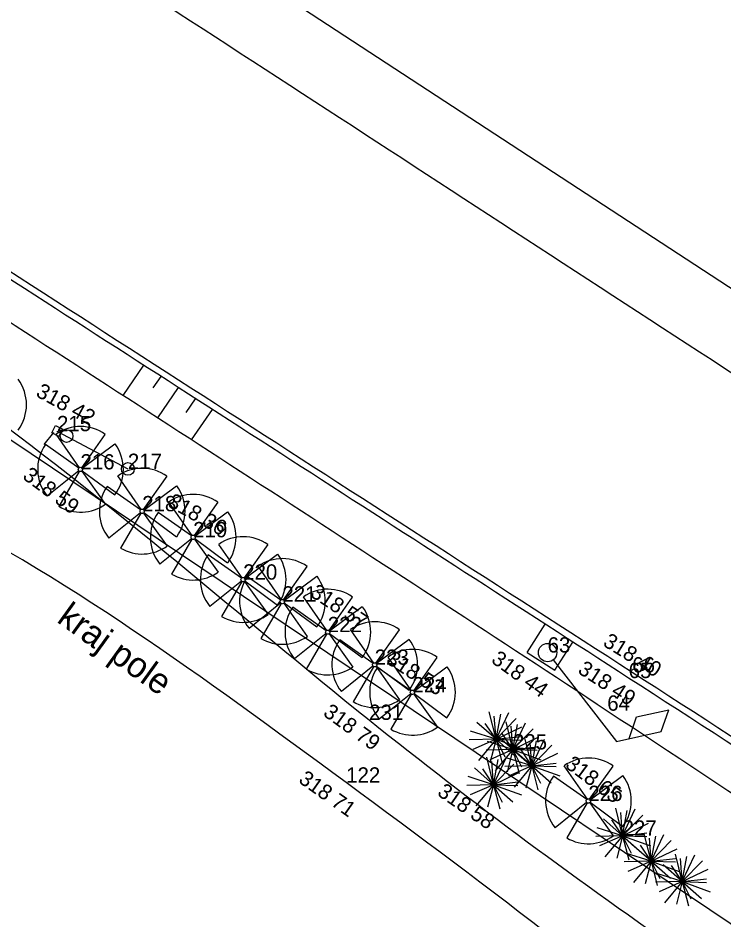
# Model space of a CAD drawing. Extents: x -742884 to -742543, y -1054677 to -1054433.
# Drawn here: x -742695.71 to -742681.87, y -1054513.42 to -1054495.74 of the extents above; entities that cross this region are included whole.
import ezdxf

# ---------------------------------------------------------------- set-up
doc = ezdxf.new("R2010")
doc.units = 0
for name, color, linetype in [('Vrstva 1', 7, 'Continuous'), ('Vrstva 10', 7, 'Continuous'), ('Vrstva 11', 7, 'Continuous'), ('Vrstva 12', 7, 'Continuous'), ('Vrstva 15', 7, 'Continuous'), ('Vrstva 16', 7, 'Continuous'), ('Vrstva 2', 7, 'Continuous'), ('Vrstva 3', 7, 'Continuous'), ('Vrstva 4', 7, 'Continuous'), ('Vrstva 50', 7, 'Continuous'), ('Vrstva 8', 7, 'Continuous')]:
    doc.layers.add(name, color=color, linetype=linetype)

# ---------------------------------------------------------------- blocks, each defined once
blk = doc.blocks.new('Z15')
at = {"layer": 'Vrstva 2'}
for p, q in [((-10, 2), (-8, 6)), ((-10, -2), (-10, 2)), ((-8, 6), (-6, 8)), ((-6, 8), (-2, 10)), ((-2, 10), (2, 10)), ((2, 10), (6, 8)), ((6, 8), (8, 6)), ((8, 6), (10, 2)), ((10, 2), (10, -2)), ((-8, -6), (-10, -2)), ((-6, -8), (-8, -6)), ((-2, -10), (-6, -8)), ((2, -10), (-2, -10)), ((6, -8), (2, -10)), ((8, -6), (6, -8)), ((10, -2), (8, -6))]:
    blk.add_line(p, q, dxfattribs=at)

msp = doc.modelspace()

# ---------------------------------------------------------------- linework, layer by layer
at = {"layer": 'Vrstva 1'}
for p, q in [((-742694.95, -1054503.84), (-742694.95, -1054503.84)), ((-742693.56, -1054504.58), (-742693.56, -1054504.58)), ((-742694.49, -1054504.59), (-742694.49, -1054504.59)), ((-742693.28, -1054505.41), (-742693.28, -1054505.41)), ((-742692.28, -1054505.92), (-742692.28, -1054505.92)), ((-742691.3, -1054506.75), (-742691.3, -1054506.75)), ((-742690.53, -1054507.18), (-742690.53, -1054507.18)), ((-742689.64, -1054507.78), (-742689.64, -1054507.78)), ((-742685.33, -1054508.18), (-742685.33, -1054508.18)), ((-742688.72, -1054508.42), (-742688.72, -1054508.42)), ((-742683.67, -1054508.57), (-742683.67, -1054508.57)), ((-742683.74, -1054508.68), (-742683.74, -1054508.68)), ((-742687.98, -1054508.96), (-742687.98, -1054508.96)), ((-742684.16, -1054509.32), (-742684.16, -1054509.32)), ((-742688.83, -1054509.5), (-742688.83, -1054509.5)), ((-742686.01, -1054510.08), (-742686.01, -1054510.08)), ((-742689.28, -1054510.73), (-742689.28, -1054510.73)), ((-742684.53, -1054511.09), (-742684.53, -1054511.09)), ((-742683.86, -1054511.77), (-742683.86, -1054511.77))]:
    msp.add_line(p, q, dxfattribs=at)
at = {"layer": 'Vrstva 10'}
for p, q in [((-742694.51, -1054504.557), (-742694.967, -1054503.898)), ((-742694.465, -1054504.557), (-742694.002, -1054503.904)), ((-742694.523, -1054504.562), (-742695.175, -1054504.103)), ((-742694.458, -1054504.566), (-742693.814, -1054504.089)), ((-742694.524, -1054504.619), (-742695.143, -1054505.116)), ((-742694.515, -1054504.627), (-742694.912, -1054505.315)), ((-742694.462, -1054504.624), (-742694.001, -1054505.274)), ((-742694.454, -1054504.615), (-742693.814, -1054505.088)), ((-742693.3, -1054505.377), (-742693.757, -1054504.718)), ((-742693.255, -1054505.377), (-742692.792, -1054504.724)), ((-742693.313, -1054505.382), (-742693.965, -1054504.923)), ((-742693.248, -1054505.386), (-742692.604, -1054504.909)), ((-742692.3, -1054505.887), (-742692.757, -1054505.228)), ((-742692.255, -1054505.887), (-742691.792, -1054505.234)), ((-742693.314, -1054505.439), (-742693.933, -1054505.936)), ((-742693.305, -1054505.447), (-742693.702, -1054506.135)), ((-742693.252, -1054505.444), (-742692.791, -1054506.094)), ((-742693.244, -1054505.435), (-742692.604, -1054505.908)), ((-742692.313, -1054505.892), (-742692.965, -1054505.433)), ((-742692.248, -1054505.896), (-742691.604, -1054505.419)), ((-742692.314, -1054505.949), (-742692.933, -1054506.446)), ((-742692.305, -1054505.957), (-742692.702, -1054506.645)), ((-742692.252, -1054505.954), (-742691.791, -1054506.604)), ((-742692.244, -1054505.945), (-742691.604, -1054506.418)), ((-742691.32, -1054506.717), (-742691.777, -1054506.058)), ((-742691.275, -1054506.717), (-742690.812, -1054506.064)), ((-742691.333, -1054506.722), (-742691.985, -1054506.263)), ((-742691.268, -1054506.726), (-742690.624, -1054506.249)), ((-742690.55, -1054507.147), (-742691.007, -1054506.488)), ((-742690.505, -1054507.147), (-742690.042, -1054506.494)), ((-742690.563, -1054507.152), (-742691.215, -1054506.693)), ((-742690.498, -1054507.156), (-742689.854, -1054506.679)), ((-742691.334, -1054506.779), (-742691.953, -1054507.276)), ((-742691.325, -1054506.787), (-742691.722, -1054507.475)), ((-742691.272, -1054506.784), (-742690.811, -1054507.434)), ((-742691.264, -1054506.775), (-742690.624, -1054507.248)), ((-742690.564, -1054507.209), (-742691.183, -1054507.706)), ((-742690.555, -1054507.217), (-742690.952, -1054507.905)), ((-742690.502, -1054507.214), (-742690.041, -1054507.864)), ((-742690.494, -1054507.205), (-742689.854, -1054507.678)), ((-742689.66, -1054507.747), (-742690.117, -1054507.088)), ((-742689.615, -1054507.747), (-742689.152, -1054507.094)), ((-742689.673, -1054507.752), (-742690.325, -1054507.293)), ((-742689.608, -1054507.756), (-742688.964, -1054507.279)), ((-742688.74, -1054508.387), (-742689.197, -1054507.728)), ((-742688.695, -1054508.387), (-742688.232, -1054507.734)), ((-742689.674, -1054507.809), (-742690.293, -1054508.306)), ((-742689.665, -1054507.817), (-742690.062, -1054508.505)), ((-742689.612, -1054507.814), (-742689.151, -1054508.464)), ((-742689.604, -1054507.805), (-742688.964, -1054508.278)), ((-742688.753, -1054508.392), (-742689.405, -1054507.933)), ((-742688.688, -1054508.396), (-742688.044, -1054507.919)), ((-742688, -1054508.927), (-742688.457, -1054508.268)), ((-742687.955, -1054508.927), (-742687.492, -1054508.274)), ((-742688.754, -1054508.449), (-742689.373, -1054508.946)), ((-742688.745, -1054508.457), (-742689.142, -1054509.145)), ((-742688.692, -1054508.454), (-742688.231, -1054509.104)), ((-742688.684, -1054508.445), (-742688.044, -1054508.918)), ((-742687.948, -1054508.936), (-742687.304, -1054508.459)), ((-742688.013, -1054508.932), (-742688.665, -1054508.473)), ((-742688.014, -1054508.989), (-742688.633, -1054509.486)), ((-742688.005, -1054508.997), (-742688.402, -1054509.685)), ((-742687.952, -1054508.994), (-742687.491, -1054509.644)), ((-742687.944, -1054508.985), (-742687.304, -1054509.458)), ((-742686.34, -1054509.88), (-742686.473, -1054509.341)), ((-742686.34, -1054509.88), (-742686.092, -1054509.355)), ((-742686.34, -1054509.88), (-742686.374, -1054509.426)), ((-742686.34, -1054509.88), (-742686.247, -1054509.389)), ((-742686.34, -1054509.88), (-742685.944, -1054509.475)), ((-742686.34, -1054509.88), (-742686.715, -1054509.551)), ((-742686.34, -1054509.88), (-742686.551, -1054509.568)), ((-742686.34, -1054509.88), (-742685.832, -1054509.635)), ((-742686.01, -1054510.08), (-742686.143, -1054509.541)), ((-742686.01, -1054510.08), (-742686.044, -1054509.626)), ((-742686.01, -1054510.08), (-742685.762, -1054509.555)), ((-742686.01, -1054510.08), (-742685.917, -1054509.589)), ((-742686.01, -1054510.08), (-742685.614, -1054509.675)), ((-742686.34, -1054509.88), (-742686.866, -1054509.894)), ((-742686.34, -1054509.88), (-742686.839, -1054509.723)), ((-742686.34, -1054509.88), (-742686.795, -1054510.082)), ((-742686.34, -1054509.88), (-742686.685, -1054510.298)), ((-742686.34, -1054509.88), (-742686.455, -1054510.321)), ((-742686.01, -1054510.08), (-742686.385, -1054509.751)), ((-742686.344, -1054509.878), (-742686.344, -1054509.878)), ((-742686.34, -1054509.88), (-742685.863, -1054509.827)), ((-742686.34, -1054509.88), (-742686.34, -1054509.88)), ((-742686.34, -1054509.88), (-742686.169, -1054510.221)), ((-742686.34, -1054509.88), (-742685.79, -1054510.08)), ((-742686.34, -1054509.88), (-742685.863, -1054509.896)), ((-742686.34, -1054509.88), (-742685.959, -1054510.215)), ((-742686.34, -1054509.88), (-742686.218, -1054510.354)), ((-742686.34, -1054509.88), (-742686.34, -1054509.88)), ((-742686.01, -1054510.08), (-742686.221, -1054509.768)), ((-742686.01, -1054510.08), (-742685.502, -1054509.835)), ((-742685.64, -1054510.4), (-742685.773, -1054509.861)), ((-742685.64, -1054510.4), (-742685.392, -1054509.875)), ((-742686.01, -1054510.08), (-742686.509, -1054509.923)), ((-742686.01, -1054510.08), (-742685.533, -1054510.027)), ((-742685.64, -1054510.4), (-742685.674, -1054509.946)), ((-742685.64, -1054510.4), (-742685.547, -1054509.909)), ((-742685.64, -1054510.4), (-742685.244, -1054509.995)), ((-742686.01, -1054510.08), (-742686.536, -1054510.094)), ((-742686.39, -1054510.77), (-742686.523, -1054510.231)), ((-742686.01, -1054510.08), (-742686.465, -1054510.282)), ((-742686.01, -1054510.08), (-742686.355, -1054510.498)), ((-742686.01, -1054510.08), (-742686.125, -1054510.521)), ((-742685.64, -1054510.4), (-742686.015, -1054510.071)), ((-742686.014, -1054510.078), (-742686.014, -1054510.078)), ((-742686.01, -1054510.08), (-742686.01, -1054510.08)), ((-742686.01, -1054510.08), (-742685.839, -1054510.421)), ((-742686.01, -1054510.08), (-742685.46, -1054510.28)), ((-742686.01, -1054510.08), (-742685.533, -1054510.096)), ((-742686.01, -1054510.08), (-742685.629, -1054510.415)), ((-742686.01, -1054510.08), (-742685.888, -1054510.554)), ((-742686.01, -1054510.08), (-742686.01, -1054510.08)), ((-742685.64, -1054510.4), (-742685.851, -1054510.088)), ((-742685.64, -1054510.4), (-742685.132, -1054510.155)), ((-742686.39, -1054510.77), (-742686.424, -1054510.316)), ((-742686.39, -1054510.77), (-742686.142, -1054510.245)), ((-742686.39, -1054510.77), (-742686.297, -1054510.279)), ((-742686.39, -1054510.77), (-742685.994, -1054510.365)), ((-742685.64, -1054510.4), (-742686.166, -1054510.414)), ((-742685.64, -1054510.4), (-742686.139, -1054510.243)), ((-742685.64, -1054510.4), (-742686.095, -1054510.602)), ((-742685.64, -1054510.4), (-742685.985, -1054510.818)), ((-742685.64, -1054510.4), (-742685.755, -1054510.841)), ((-742685.644, -1054510.398), (-742685.644, -1054510.398)), ((-742685.64, -1054510.4), (-742685.163, -1054510.347)), ((-742685.64, -1054510.4), (-742685.64, -1054510.4)), ((-742685.64, -1054510.4), (-742685.469, -1054510.741)), ((-742685.64, -1054510.4), (-742685.09, -1054510.6)), ((-742685.64, -1054510.4), (-742685.163, -1054510.416)), ((-742685.64, -1054510.4), (-742685.259, -1054510.735)), ((-742685.64, -1054510.4), (-742685.518, -1054510.874)), ((-742685.64, -1054510.4), (-742685.64, -1054510.4)), ((-742684.55, -1054511.057), (-742685.007, -1054510.398)), ((-742684.505, -1054511.057), (-742684.042, -1054510.404)), ((-742686.39, -1054510.77), (-742686.765, -1054510.441)), ((-742686.39, -1054510.77), (-742686.601, -1054510.458)), ((-742686.39, -1054510.77), (-742685.882, -1054510.525)), ((-742684.498, -1054511.066), (-742683.854, -1054510.589)), ((-742686.39, -1054510.77), (-742686.916, -1054510.784)), ((-742686.39, -1054510.77), (-742686.889, -1054510.613)), ((-742686.39, -1054510.77), (-742686.845, -1054510.972)), ((-742686.39, -1054510.77), (-742686.735, -1054511.188)), ((-742686.39, -1054510.77), (-742686.505, -1054511.211)), ((-742686.394, -1054510.768), (-742686.394, -1054510.768)), ((-742686.39, -1054510.77), (-742685.913, -1054510.717)), ((-742686.39, -1054510.77), (-742686.39, -1054510.77)), ((-742686.39, -1054510.77), (-742686.219, -1054511.111)), ((-742686.39, -1054510.77), (-742685.84, -1054510.97)), ((-742686.39, -1054510.77), (-742685.913, -1054510.786)), ((-742686.39, -1054510.77), (-742686.009, -1054511.105)), ((-742686.39, -1054510.77), (-742686.268, -1054511.244)), ((-742686.39, -1054510.77), (-742686.39, -1054510.77)), ((-742684.563, -1054511.062), (-742685.215, -1054510.603)), ((-742684.564, -1054511.119), (-742685.183, -1054511.616)), ((-742684.502, -1054511.124), (-742684.041, -1054511.774)), ((-742684.494, -1054511.115), (-742683.854, -1054511.588)), ((-742684.555, -1054511.127), (-742684.952, -1054511.815)), ((-742683.86, -1054511.77), (-742683.993, -1054511.231)), ((-742683.86, -1054511.77), (-742683.612, -1054511.245)), ((-742683.86, -1054511.77), (-742683.767, -1054511.279)), ((-742683.86, -1054511.77), (-742684.235, -1054511.441)), ((-742683.86, -1054511.77), (-742684.071, -1054511.458)), ((-742683.86, -1054511.77), (-742683.894, -1054511.316)), ((-742683.86, -1054511.77), (-742683.464, -1054511.365)), ((-742683.86, -1054511.77), (-742684.359, -1054511.613)), ((-742683.86, -1054511.77), (-742683.352, -1054511.525)), ((-742683.86, -1054511.77), (-742684.386, -1054511.784)), ((-742683.86, -1054511.77), (-742684.315, -1054511.972)), ((-742683.86, -1054511.77), (-742684.205, -1054512.188)), ((-742683.86, -1054511.77), (-742683.975, -1054512.211)), ((-742683.864, -1054511.768), (-742683.864, -1054511.768)), ((-742683.86, -1054511.77), (-742683.383, -1054511.717)), ((-742683.86, -1054511.77), (-742683.86, -1054511.77)), ((-742683.86, -1054511.77), (-742683.689, -1054512.111)), ((-742683.86, -1054511.77), (-742683.31, -1054511.97)), ((-742683.86, -1054511.77), (-742683.383, -1054511.786)), ((-742683.86, -1054511.77), (-742683.479, -1054512.105)), ((-742683.86, -1054511.77), (-742683.738, -1054512.244)), ((-742683.86, -1054511.77), (-742683.86, -1054511.77)), ((-742683.3, -1054512.27), (-742683.433, -1054511.731)), ((-742683.3, -1054512.27), (-742683.334, -1054511.816)), ((-742683.3, -1054512.27), (-742683.052, -1054511.745)), ((-742683.3, -1054512.27), (-742683.207, -1054511.779)), ((-742683.3, -1054512.27), (-742683.675, -1054511.941)), ((-742683.3, -1054512.27), (-742683.511, -1054511.958)), ((-742683.3, -1054512.27), (-742682.904, -1054511.865)), ((-742683.3, -1054512.27), (-742683.799, -1054512.113)), ((-742683.3, -1054512.27), (-742682.792, -1054512.025)), ((-742682.69, -1054512.67), (-742682.823, -1054512.131)), ((-742682.69, -1054512.67), (-742682.442, -1054512.145)), ((-742682.69, -1054512.67), (-742682.597, -1054512.179)), ((-742683.3, -1054512.27), (-742683.826, -1054512.284)), ((-742683.3, -1054512.27), (-742683.755, -1054512.472)), ((-742683.3, -1054512.27), (-742683.645, -1054512.688)), ((-742683.3, -1054512.27), (-742683.415, -1054512.711)), ((-742683.304, -1054512.268), (-742683.304, -1054512.268)), ((-742683.3, -1054512.27), (-742682.823, -1054512.217)), ((-742683.3, -1054512.27), (-742683.3, -1054512.27)), ((-742683.3, -1054512.27), (-742683.129, -1054512.611)), ((-742683.3, -1054512.27), (-742682.75, -1054512.47)), ((-742683.3, -1054512.27), (-742682.823, -1054512.286)), ((-742683.3, -1054512.27), (-742682.919, -1054512.605)), ((-742683.3, -1054512.27), (-742683.178, -1054512.744)), ((-742683.3, -1054512.27), (-742683.3, -1054512.27)), ((-742682.69, -1054512.67), (-742683.065, -1054512.341)), ((-742682.69, -1054512.67), (-742682.901, -1054512.358)), ((-742682.69, -1054512.67), (-742682.724, -1054512.216)), ((-742682.69, -1054512.67), (-742682.294, -1054512.265)), ((-742682.69, -1054512.67), (-742683.189, -1054512.513)), ((-742682.69, -1054512.67), (-742682.182, -1054512.425)), ((-742682.69, -1054512.67), (-742683.216, -1054512.684)), ((-742682.69, -1054512.67), (-742683.145, -1054512.872)), ((-742682.69, -1054512.67), (-742683.035, -1054513.088)), ((-742682.69, -1054512.67), (-742682.805, -1054513.111)), ((-742682.694, -1054512.668), (-742682.694, -1054512.668)), ((-742682.69, -1054512.67), (-742682.213, -1054512.617)), ((-742682.69, -1054512.67), (-742682.69, -1054512.67)), ((-742682.69, -1054512.67), (-742682.519, -1054513.011)), ((-742682.69, -1054512.67), (-742682.14, -1054512.87)), ((-742682.69, -1054512.67), (-742682.213, -1054512.686)), ((-742682.69, -1054512.67), (-742682.309, -1054513.005)), ((-742682.69, -1054512.67), (-742682.568, -1054513.144)), ((-742682.69, -1054512.67), (-742682.69, -1054512.67))]:
    msp.add_line(p, q, dxfattribs=at)
for centre, start, end in [((-742696.388, -1054503.318), 323.4756, 36.2971), ((-742694.488, -1054504.588), 54.7465, 124.8105), ((-742694.489, -1054504.586), 144.8767, 218.9336), ((-742694.488, -1054504.588), 323.4756, 36.2971), ((-742693.278, -1054505.408), 54.7465, 124.8105), ((-742693.279, -1054505.406), 144.8767, 218.9336), ((-742693.278, -1054505.408), 323.4756, 36.2971), ((-742692.278, -1054505.918), 54.7465, 124.8105), ((-742694.488, -1054504.588), 239.6151, 305.4552), ((-742692.279, -1054505.916), 144.8767, 218.9336), ((-742692.278, -1054505.918), 323.4756, 36.2971), ((-742691.298, -1054506.748), 54.7465, 124.8105), ((-742693.278, -1054505.408), 239.6151, 305.4552), ((-742691.299, -1054506.746), 144.8767, 218.9336), ((-742690.528, -1054507.178), 54.7465, 124.8105), ((-742691.298, -1054506.748), 323.4756, 36.2971), ((-742692.278, -1054505.918), 239.6151, 305.4552), ((-742690.529, -1054507.176), 144.8767, 218.9336), ((-742690.528, -1054507.178), 323.4756, 36.2971), ((-742689.638, -1054507.778), 54.7465, 124.8105), ((-742689.639, -1054507.776), 144.8767, 218.9336), ((-742689.638, -1054507.778), 323.4756, 36.2971), ((-742691.298, -1054506.748), 239.6151, 305.4552), ((-742688.718, -1054508.418), 54.7465, 124.8105), ((-742690.528, -1054507.178), 239.6151, 305.4552), ((-742688.719, -1054508.416), 144.8767, 218.9336), ((-742688.718, -1054508.418), 323.4756, 36.2971), ((-742687.978, -1054508.958), 54.7465, 124.8105), ((-742689.638, -1054507.778), 239.6151, 305.4552), ((-742687.978, -1054508.958), 323.4756, 36.2971), ((-742687.979, -1054508.956), 144.8767, 218.9336), ((-742688.718, -1054508.418), 239.6151, 305.4552), ((-742687.978, -1054508.958), 239.6151, 305.4552), ((-742684.528, -1054511.088), 54.7465, 124.8105), ((-742684.528, -1054511.088), 323.4756, 36.2971), ((-742684.529, -1054511.086), 144.8767, 218.9336), ((-742684.528, -1054511.088), 239.6151, 305.4552)]:
    msp.add_arc(centre, 0.84, start, end, dxfattribs=at)
at = {"layer": 'Vrstva 11'}
for p, q in [((-742693.254, -1054502.547), (-742693.661, -1054503.137)), ((-742692.914, -1054502.766), (-742693.069, -1054502.991)), ((-742692.575, -1054502.984), (-742692.981, -1054503.577)), ((-742692.419, -1054503.473), (-742692.234, -1054503.203)), ((-742692.311, -1054504.011), (-742691.902, -1054503.417))]:
    msp.add_line(p, q, dxfattribs=at)
for points in [[(-742776.7, -1054542.68), (-742764.01, -1054527.79), (-742751.11, -1054512.75), (-742737.61, -1054496.47), (-742726.42, -1054483.98), (-742725.9, -1054484.03), (-742714, -1054491.86), (-742704.819, -1054497.481), (-742700.94, -1054500.269), (-742696.44, -1054503.39), (-742688.83, -1054509.5), (-742682.54, -1054514.17), (-742675.15, -1054519.77), (-742673.01, -1054522.11), (-742671.05, -1054524.7)], [(-742696.97, -1054500.991), (-742684.16, -1054509.32), (-742669.06, -1054519.4)], [(-742641.45, -1054542), (-742646.08, -1054542.32), (-742650.28, -1054545.1), (-742653.63, -1054549.14), (-742658.66, -1054557.13), (-742664.13, -1054565.84), (-742667.81, -1054569.62), (-742669.76, -1054570.07), (-742674.4, -1054567.88), (-742684.66, -1054562.03), (-742693.02, -1054556.88), (-742694.43, -1054554.37), (-742693.99, -1054552.67), (-742684.52, -1054539.64), (-742677.51, -1054529.95), (-742676.26, -1054526.54), (-742677.27, -1054522.39), (-742681.19, -1054517.29), (-742689.28, -1054510.73), (-742697.86, -1054505.14), (-742704.02, -1054502.75), (-742713.11, -1054501.07), (-742723.98, -1054503.51), (-742736.77, -1054510.1), (-742745.39, -1054515.75), (-742752.81, -1054521.82), (-742762.72, -1054531.38), (-742770.54, -1054539.36), (-742775.54, -1054544.64)]]:
    msp.add_spline(points, degree=3, dxfattribs=at)
at = {"layer": 'Vrstva 12'}
for p, q in [((-742685.731, -1054508.176), (-742685.375, -1054507.624)), ((-742685.19, -1054508.524), (-742684.835, -1054507.973)), ((-742685.731, -1054508.176), (-742685.19, -1054508.524))]:
    msp.add_line(p, q, dxfattribs=at)
for points in [[(-742685.219, -1054508.323), (-742683.98, -1054509.922)], [(-742683.587, -1054509.44), (-742682.955, -1054509.302)], [(-742683.1, -1054509.728), (-742682.955, -1054509.302)], [(-742683.732, -1054509.867), (-742683.587, -1054509.44)], [(-742683.98, -1054509.922), (-742683.1, -1054509.728)]]:
    msp.add_lwpolyline(points, dxfattribs=at)
msp.add_circle((-742685.33, -1054508.18), 0.18, dxfattribs=at)
at = {"layer": 'Vrstva 16'}
for p, q in [((-742695.054, -1054503.871), (-742694.979, -1054503.728)), ((-742694.912, -1054503.944), (-742695.054, -1054503.871)), ((-742694.979, -1054503.728), (-742694.838, -1054503.801)), ((-742694.95, -1054503.84), (-742693.56, -1054504.58)), ((-742694.912, -1054503.944), (-742694.838, -1054503.801))]:
    msp.add_line(p, q, dxfattribs=at)
for centre in [(-742694.762, -1054503.936), (-742693.56, -1054504.58)]:
    msp.add_circle(centre, 0.125, dxfattribs=at)
at = {"layer": 'Vrstva 4'}
for points in [[(-742718.8, -1054478.84), (-742709.4, -1054484.88), (-742695.99, -1054493.43), (-742680.4, -1054503.55), (-742661.01, -1054516), (-742635.78, -1054532.31)], [(-742668.427, -1054518.574), (-742683.74, -1054508.68), (-742696.59, -1054500.4), (-742699.13, -1054498.77), (-742713.15, -1054489.73), (-742724.623, -1054482.289)], [(-742668.31, -1054518.5), (-742683.67, -1054508.57), (-742699.06, -1054498.66), (-742713.08, -1054489.62), (-742724.57, -1054482.17)]]:
    msp.add_spline(points, degree=3, dxfattribs=at)
at = {"layer": 'Vrstva 50'}
msp.add_line((-742697.33, -1054490.84), (-742680.73, -1054501.69), dxfattribs=at)
msp.add_lwpolyline([(-742724.95, -1054484.46), (-742672.19, -1054519.91), (-742671.42, -1054521.73), (-742671.38, -1054524.18), (-742670.45, -1054526.06)], dxfattribs=at)
at = {"layer": 'Vrstva 8'}
msp.add_line((-742695.2, -1054504.1), (-742695.011, -1054503.867), dxfattribs=at)

# ---------------------------------------------------------------- block references
at = {"layer": 'Vrstva 10', "xscale": 0.004197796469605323, "yscale": 0.004197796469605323, "rotation": -30.671756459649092}
for p in [(-742694.49, -1054504.59), (-742693.28, -1054505.41), (-742692.28, -1054505.92), (-742691.3, -1054506.75), (-742690.53, -1054507.18), (-742689.64, -1054507.78), (-742688.72, -1054508.42), (-742687.98, -1054508.96), (-742684.53, -1054511.09)]:
    msp.add_blockref('Z15', p, dxfattribs=at)

# ---------------------------------------------------------------- texts
at = {"layer": 'Vrstva 15'}
msp.add_text('kraj pole', height=0.4992, rotation=324.2494, dxfattribs=at).set_placement((-742694.974, -1054507.569))
at = {"layer": 'Vrstva 2'}
for s, p in [('215', (-742694.95, -1054503.84)), ('216', (-742694.49, -1054504.59)), ('217', (-742693.56, -1054504.58)), ('218', (-742693.28, -1054505.41)), ('219', (-742692.28, -1054505.92)), ('220', (-742691.3, -1054506.75)), ('221', (-742690.53, -1054507.18)), ('222', (-742689.64, -1054507.78)), ('63', (-742685.33, -1054508.18)), ('223', (-742688.72, -1054508.42)), ('66', (-742683.67, -1054508.57)), ('65', (-742683.74, -1054508.68)), ('224', (-742687.98, -1054508.96)), ('64', (-742684.16, -1054509.32)), ('231', (-742688.83, -1054509.5)), ('225', (-742686.01, -1054510.08)), ('122', (-742689.28, -1054510.73)), ('226', (-742684.53, -1054511.09)), ('227', (-742683.86, -1054511.77))]:
    msp.add_text(s, height=0.3, dxfattribs=at).set_placement(p)
at = {"layer": 'Vrstva 3'}
for s, rotation, p in [('318 42 ', 331.4172, (-742695.383, -1054503.145)), ('318 59 ', 323.5028, (-742695.643, -1054504.757)), ('318 36 ', 330.8431, (-742692.802, -1054505.301)), ('318 57 ', 326.6376, (-742690.006, -1054507.064)), ('318 40 ', 328.4404, (-742684.263, -1054508.034)), ('318 53 ', 327.3039, (-742688.518, -1054508.373)), ('318 44 ', 324.1762, (-742686.454, -1054508.361)), ('318 49 ', 326.8275, (-742684.756, -1054508.568)), ('318 79 ', 324.3653, (-742689.75, -1054509.402)), ('318 65 ', 323.2858, (-742685.003, -1054510.419)), ('318 71 ', 324.7824, (-742690.232, -1054510.713)), ('318 58 ', 325.3992, (-742687.511, -1054510.965))]:
    msp.add_text(s, height=0.3, rotation=rotation, dxfattribs=at).set_placement(p)

doc.saveas('drawing.dxf')
